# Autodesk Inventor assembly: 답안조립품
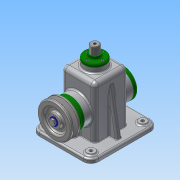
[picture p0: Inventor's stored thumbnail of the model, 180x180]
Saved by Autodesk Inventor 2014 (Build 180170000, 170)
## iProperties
Created: 2015-12
Part Number: 답안조립품
Document SubType Name: Assembly
Designer: Administrator
Author: Administrator
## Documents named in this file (19)
- D:\451225V1010\답안조립품.iam
- D:\451225V1010\1-본체.ipt
- D:\451225V1010\베어링 15 x 35 x 11.ipt
- D:\451225V1010\뒤커버.ipt
- D:\451225V1010\볼트 M4 x 10.ipt
- D:\451225V1010\앞커버.ipt
- D:\451225V1010\오일실 15 25 7.ipt
- D:\451225V1010\볼트 M3 x 8.ipt
- D:\451225V1010\상부부시.ipt
- D:\451225V1010\편심축.ipt
- D:\451225V1010\키 5 x 5 x 14.ipt
- D:\451225V1010\V-벨트풀리.ipt
- D:\451225V1010\볼트 M6 x 12.ipt
- D:\451225V1010\와셔.ipt
- D:\451225V1010\멈춤링 15 x 1.ipt
- D:\451225V1010\슬라이드바.ipt
- D:\451225V1010\멈춤링 6 x 5.ipt
- D:\451225V1010\링크.ipt
- D:\451225V1010\고정핀.ipt
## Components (16 placed, 6 different names)
1. 1-본체:1
2. V-벨트풀리:1 — 플러쉬:1, 각도:2
3. ISO 4018 M6 x 12:1
4. 고정핀:1
5. ISO 4762 M4 x 10:1
6. ISO 4762 M4 x 10:2
7. ISO 4762 M4 x 10:3
8. ISO 4762 M4 x 10:4
9. ISO 4762 M4 x 10:5
10. ISO 4762 M4 x 10:6
11. ISO 4762 M4 x 10:7
12. ISO 4762 M4 x 10:8
13. ISO 4762 M3 x 8:1
14. ISO 4762 M3 x 8:2
15. ISO 4762 M3 x 8:3
16. ISO 4762 M3 x 8:4
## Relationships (2: Flush 1, Angle 1)
- 플러쉬:1 [Flush]: V-벨트풀리:1
- 각도:2 [Angle]: V-벨트풀리:1
